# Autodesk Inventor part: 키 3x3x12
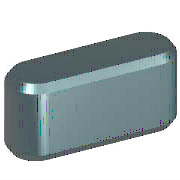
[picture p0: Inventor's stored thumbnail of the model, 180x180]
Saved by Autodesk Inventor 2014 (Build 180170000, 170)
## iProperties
Created: 2012-02
Part Number: 키 3x3x12
Material: 강철, 연강
Description: 키 및 해당 키홈
Document SubType Name: Modeling
Standard: KS B 1311
Designer: mduedu
Standards Organization: KS
Language: ko-KR
Size Designation: 3 x 3 x 12
Categories: <MemberInstance><Categories><Category DisplayName="샤프트 부품" InternalName="7f7aeb1f-a693-4053-b835-cee3144e0d98" Mnemonic="SHFT"><Category DisplayName="키" Interna
Density: 1 g/cm^3
Appearance: 노란색
IsCustomPart: 1
Author: mduedu
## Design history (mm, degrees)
workplane "Work Plane1"
workplane "Work Plane2"
sketch "스케치1"
  geometry: L1 (1.5, 1.5)-(10.5, 1.5); L2 (10.5, -1.5)-(1.5, -1.5); L3 (0, 9.4)-(0, -7.4) reference; L4 (-5, 0)-(30, 0) reference; L5 (12, 0)-(12, 7); A1 r 1.5 centre (1.5, 0) between (1.5, 1.5) and (1.5, -1.5); A2 r 1.5 centre (10.5, 0) between (10.5, -1.5) and (10.5, 1.5)
  constraints: 6 end point, 5 point on circle, 4 tangent, 3 point on line, 2 centre point, 1 horizontal, 1 parallel, 1 perpendicular
  dimensions: "d0" = 1.5 radius of A1 (= 0.5 x PB); "d13" = 1.5 radius of A2 (= 0.5 x PB); "d14" = 12 distance between parallel lines of L5 L3 (= NLG)
extrude "본체1" new body sketch "스케치1" taper "d3" = 0 deg; stored distance "d4" = 10
workplane "Work Plane3"
body "Solid1"
chamfer "모따기1" distance "d8" = 0.25 (= PHH); stored, may be unused: second distance "d9" = 0.25 (= PHH), angle "d15" = 45 deg
other parameters: "d1" = -1.8 (= -PNT), "d2" = 1.2 (= PH - PNT), "NLG" = 12 [user parameter; used in 3 equation terms], "PB" = 3 [user parameter; used in 2 equation terms], "PNT" = 1.8 [user parameter; used in 2 equation terms], "PH" = 3 [user parameter; used in 1 equation term], "PHH" = 0.25 [user parameter; used in 2 equation terms], "d10" = 0, "d16" = 0, "d17" = 0, "d18" = 0, "WDMIN" = 8 [user parameter], "PLB2" = 12 (= NLG) [user parameter], "PLB1" = 12 (= NLG) [user parameter], "RR" = 0.08 [user parameter], "PUEB" = 1.4 [user parameter]
